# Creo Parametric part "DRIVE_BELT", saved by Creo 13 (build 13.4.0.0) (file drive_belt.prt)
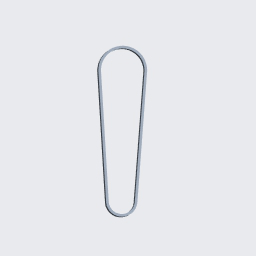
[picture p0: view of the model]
Units: millimeter Newton Second (mmNs); MM, TONNE, SECS

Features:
  1. datum plane "RIGHT"
  2. datum plane "TOP"
  3. datum plane "FRONT"
  4. coordinate system
  5. protrusion
  6. datum axis
  7. datum axis

Surfaces: 6 plane, 4 cylinder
